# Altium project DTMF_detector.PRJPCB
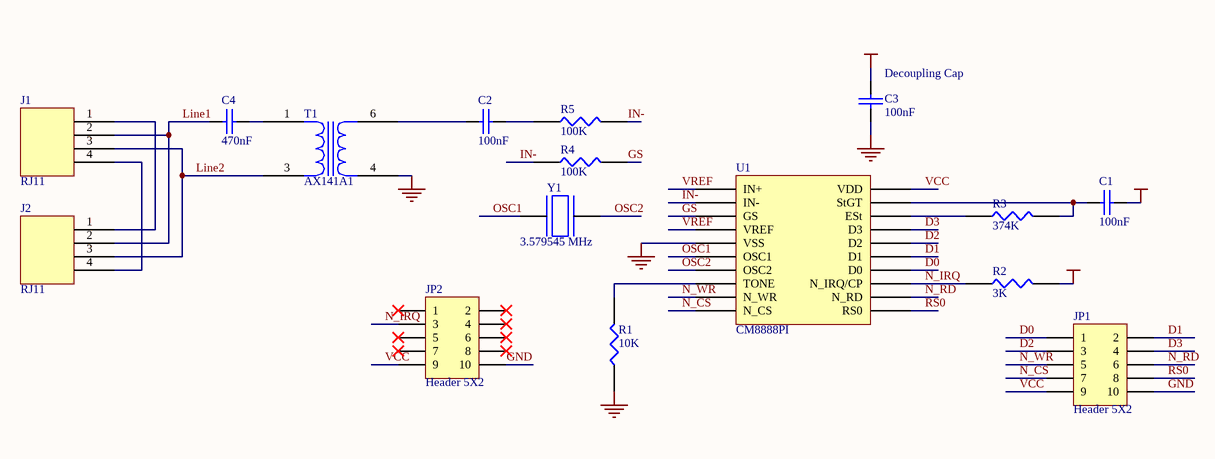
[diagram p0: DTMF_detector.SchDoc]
1 sheet, 16 parts. Net scope: global (net labels, ports and power ports of the same name join across sheets).
Board file: DTMF_detector_20060530.PcbDoc

## Sheet DTMF_detector.SchDoc
size B

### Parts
C1  100nF  [CAP Rec/0.1]
C2  100nF  [CAP Rec/0.1]
C3  100nF  [CAP Rec/0.1]
C4  470nF  [CAP Rec/0.1]
J1  RJ11  [RJ11]
J2  RJ11  [RJ11]
JP1  Header 5X2  [HDR2X5]
JP2  Header 5X2  [HDR2X5]
R1  10K  [RES]
R2  3K  [RES]
R3  374K  [RES]
R4  100K  [RES]
R5  100K  [RES]
T1  AX141A1  [TRAFO 1:1]
U1  CM8888PI  [DIP20]
Y1  3.579545 MHz  [XTAL1]

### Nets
GND: C3.2 JP1.10 JP2.10 R1.1 T1.4 U1.5(VSS)
VCC: C1.1 C3.1 JP1.9 JP2.9 R2.2 U1.20(VDD)
D0: JP1.1 U1.14(D0)
D1: JP1.2 U1.15(D1)
D2: JP1.3 U1.16(D2)
D3: JP1.4 U1.17(D3)
GS: R4.2 U1.3(GS)
IN-: R4.1 R5.2 U1.2(IN-)
Line1: C4.1 J1.2 J2.2
Line2: J1.3 J2.3 T1.3
N_CS: JP1.7 U1.10(N_CS)
N_IRQ: JP2.3 R2.1 U1.13(N_IRQ/CP)
N_RD: JP1.6 U1.12(N_RD)
N_WR: JP1.5 U1.9(N_WR)
OSC1: U1.6(OSC1) Y1.1
OSC2: U1.7(OSC2) Y1.2
RS0: JP1.8 U1.11(RS0)
VREF: U1.1(IN+) U1.4(VREF)
NetC1_2: C1.2 R3.2 U1.19(StGT)
NetC2_1: C2.1 T1.6
NetC2_2: C2.2 R5.1
NetC4_2: C4.2 T1.1
NetJ1_1: J1.1 J2.1
NetJ1_4: J1.4 J2.4
NetR1_2: R1.2 U1.8(TONE)
NetR3_1: R3.1 U1.18(ESt)

Not connected (* = marked no-connect by the designer): JP2 1* 2* 4* 5* 6* 7* 8*

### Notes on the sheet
- (near C3) Decoupling Cap

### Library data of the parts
C1-C4 = CAP: Capacitor
J1 J2 = RJ11: Telephone Connector
JP1 JP2 = Header 5X2: Header, 5-Pin, Dual row; Manufacturer: Generic Components; Class I: Connector
R1-R5 = RES
T1 = AX141: Telephone Coupling Transformer, 1:1, 600 Ohm
U1 = CM8888PI: DTMF Transceiver
Y1 = XTAL1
